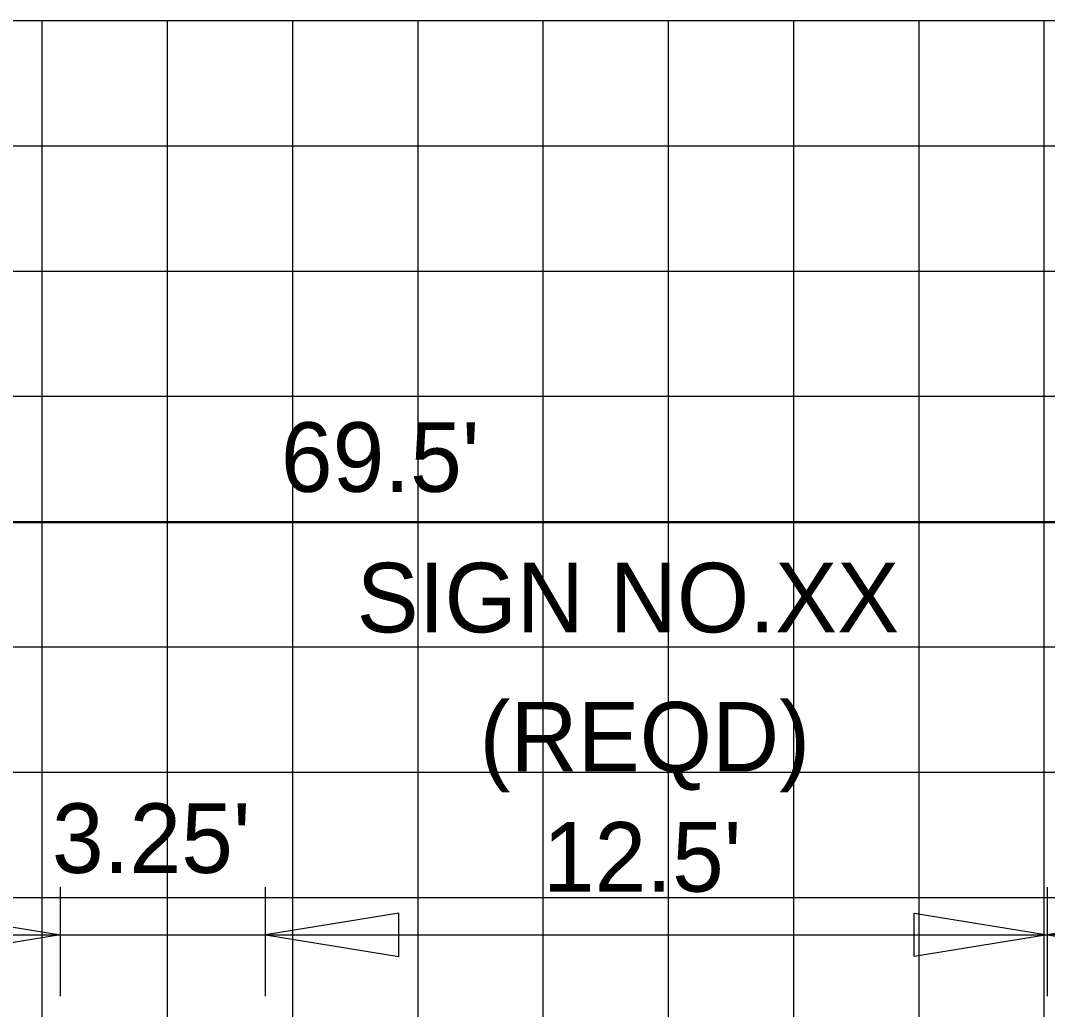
# Model space of a CAD drawing. Extents: x 2193008 to 2198143, y 1236112 to 1237864.
# Drawn here: x 2194765.34 to 2194781.74, y 1237207.32 to 1237223.11 of the extents above; entities that cross this region are included whole.
import ezdxf

# ---------------------------------------------------------------- set-up
doc = ezdxf.new("R2010")
doc.units = 0
for name, color, linetype in [('3', 7, 'Continuous'), ('GSDIMS', 7, 'Continuous'), ('Level 55', 7, 'Continuous'), ('Level 62', 7, 'Continuous')]:
    doc.layers.add(name, color=color, linetype=linetype)

msp = doc.modelspace()

# ---------------------------------------------------------------- linework, layer by layer
at = {"layer": '3'}
msp.add_line((2194736.688, 1237215.094), (2194806.188, 1237215.094), dxfattribs=at)
at = {"layer": 'GSDIMS'}
for p, q in [((2194765.981, 1237207.526), (2194765.981, 1237209.267)), ((2194769.252, 1237207.526), (2194769.252, 1237209.267)), ((2194781.739, 1237207.526), (2194781.739, 1237209.267)), ((2194749.497, 1237208.509), (2194765.981, 1237208.509)), ((2194765.981, 1237208.509), (2194769.252, 1237208.509)), ((2194769.252, 1237208.509), (2194781.739, 1237208.509)), ((2194805.688, 1237208.509), (2194781.739, 1237208.509))]:
    msp.add_line(p, q, dxfattribs=at)
for points in [[(2194765.981, 1237208.509), (2194763.852, 1237208.162), (2194763.852, 1237208.856)], [(2194769.252, 1237208.509), (2194771.38, 1237208.162), (2194771.38, 1237208.856)], [(2194781.739, 1237208.509), (2194779.611, 1237208.162), (2194779.611, 1237208.856)], [(2194781.739, 1237208.509), (2194783.867, 1237208.162), (2194783.867, 1237208.856)]]:
    msp.add_lwpolyline(points, close=True, dxfattribs=at)
at = {"layer": 'Level 62'}
for p, q in [((2194697.688, 1237223.106), (2194827.688, 1237223.106)), ((2194765.688, 1237163.106), (2194765.688, 1237223.106)), ((2194767.688, 1237163.106), (2194767.688, 1237223.106)), ((2194769.688, 1237163.106), (2194769.688, 1237223.106)), ((2194771.688, 1237163.106), (2194771.688, 1237223.106)), ((2194773.688, 1237163.106), (2194773.688, 1237223.106)), ((2194775.688, 1237163.106), (2194775.688, 1237223.106)), ((2194777.688, 1237163.106), (2194777.688, 1237223.106)), ((2194779.688, 1237163.106), (2194779.688, 1237223.106)), ((2194781.688, 1237163.106), (2194781.688, 1237223.106)), ((2194697.688, 1237221.106), (2194827.688, 1237221.106)), ((2194697.688, 1237219.106), (2194827.688, 1237219.106)), ((2194697.688, 1237217.106), (2194827.688, 1237217.106)), ((2194697.688, 1237215.106), (2194827.688, 1237215.106)), ((2194697.688, 1237213.106), (2194827.688, 1237213.106)), ((2194697.688, 1237211.106), (2194827.688, 1237211.106)), ((2194697.688, 1237209.106), (2194827.688, 1237209.106))]:
    msp.add_line(p, q, dxfattribs=at)

# ---------------------------------------------------------------- texts
at = {"layer": 'Level 55'}
for s, p in [("69.5'", (2194769.498, 1237215.581)), ('SIGN NO.XX', (2194770.707, 1237213.337)), ('(REQD)', (2194772.67, 1237211.116)), ("3.25'", (2194765.842, 1237209.496)), ("12.5'", (2194773.68, 1237209.197))]:
    msp.add_text(s, height=1.1105, dxfattribs=at).set_placement(p)

doc.saveas('drawing.dxf')
